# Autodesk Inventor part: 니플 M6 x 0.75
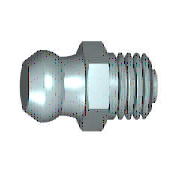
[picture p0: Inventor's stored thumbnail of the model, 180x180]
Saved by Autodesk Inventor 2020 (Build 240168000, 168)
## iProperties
Created: 2012-02
Part Number: 니플 M6 x 0.75
Material: 강철, 연강
Description: 윤활 니플, 원추 유형 A
Document SubType Name: Modeling
Standard: JIS B 1575
Designer: mduedu
Standards Organization: JIS
Language: ko-KR
Size Designation: MT 6 x 0.75
Categories: <MemberInstance><Categories><Category DisplayName="기타 부품" InternalName="5aa15e00-363f-49f2-933f-16f664388e3f" Mnemonic="OTHER"><Category DisplayName="그리스 부속품" I
Density: 7.86 g/cm^3
Mass: 3.2546 g
Surface Area: 3.29319 cm^2
Volume: 0.414071 cm^3
Appearance: 금색
IsCustomPart: 1
Author: mduedu
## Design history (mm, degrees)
sketch "스케치1"
  geometry: L1 (-8.8, 0)-(-8.8, 2.4); L2 (-8.8, 2.4)-(-7.335, 3.202); L3 (-8.8, 0)-(4.7, 0); L4 (4.7, 0)-(4.7, 1.5); L5 (4.7, 1.5)-(4, 1.5); L6 (4, 1.5)-(4, 3); L7 (4, 3)-(0, 3); L8 (-11.5, 0)-(7.4, 0) reference; L9 (0, -1.733)-(0, 10.398) reference; L10 (-3, 3.5)-(0, 3.5); L11 (0, 3.5)-(0, 3); A1 r 3.3 centre (-6.535, 0) between (-4.789, 2.8) and (-7.335, 3.202); A2 r 6 centre (-6.053, 8.665) between (-4.789, 2.8) and (-3, 3.5)
  constraints: 18 end point, 5 perpendicular, 4 point on circle, 2 centre point, 2 parallel, 2 point on line, 1 collinear, 1 vertical
  dimensions: "d0" = 13.5 distance between parallel lines of L1 L4 (= GL); "d1" = 5.6 diameter of A1.start L3 (= KGB2); "d2" = 0.7 distance between parallel lines of L4 L6 (= PHH); "d3" = 3 diameter of L5 L3 (= 0.5 x NND); "d4" = 6 diameter of L7 L3 (= NND); "d5" = 6.6 dimension on A1 L3 (= KR); "d6" = 4.8 diameter of L1.end L3 (= KGB1); "d7" = 6 radius of A2 (= RBN); "d11" = 7 diameter of L10.start L3 (= SW); "d14" = 3 distance of L10.start L10.end (= KOH); "d15" = 4 distance between parallel lines of L6 L11 (= NLG); "d61" = 7.33505 distance from line of L9 L2.end (computed from KGB1, KR, PHH, GL, NLG, VERS); "d62" = 6.53505 distance from line of L9 A1.centre (computed from NLG, GL, PHH, KR, KGB1)
revolve "본체" sketch "스케치1" stored, may be unused: angle "d25" = 90 deg
sketch "스케치2"
  geometry: L1 (2.021, 3.5)-(4.041, 0); L2 (4.041, 0)-(2.021, -3.5); L3 (2.021, -3.5)-(-2.021, -3.5); L4 (-2.021, -3.5)-(-4.041, 0); L5 (-4.041, 0)-(-2.021, 3.5); L6 (-2.021, 3.5)-(2.021, 3.5); C1 r 3.5 at (0, 0) reference; 1 further point
  constraints: 12 end point, 1 coincident, 1 horizontal, 1 tangent, 11 other
extrude "머리" join sketch "스케치2" distance "d17" = 3 (= KOH); taper "d18" = 0 deg
sketch "스케치3"
  geometry: L1 (2.687, 4.041)-(3, 4.041); L2 (3, 4.041)-(3, 3.5); L3 (3, 3.5)-(2.687, 4.041); L4 (0.313, 4.041)-(0, 4.041); L5 (0, 4.041)-(0, 3.5); L6 (0, 3.5)-(0.313, 4.041); L7 (3.6, 0)-(-0.6, 0) reference; L8 (0, 4.041)-(0, 2.021) reference; L9 (0, 4.041)-(3, 4.041) reference; L10 (3, 3.031)-(3, 4.041) reference
  constraints: 12 end point, 4 collinear, 3 perpendicular, 1 horizontal
  dimensions: "d19" = 3.5 distance from line of L5.end L7 (= 0.5 x SW); "d20" = 3.5 distance from line of L2.end L7 (= 0.5 x SW); "d21" = 30 deg angle of L6 L5; "d22" = 30 deg angle of L2 L3
revolve "모따기1" sketch "스케치3" stored, may be unused: angle "d56" = 90 deg
body "Solid1"
fillet "모깎기1" dims "d8" = 0.2 (= RR)
feature "스레드1" dims "d9" = 3.53991 (= NLG - GAL), "d10" = 0
chamfer "모따기2" distance "d23" = 0.46009 (= -0.5 x GD1 + 0.5 x NND); stored, may be unused: angle "d24" = 45 deg, second distance "d59" = 0.46009 (= -0.5 x GD1 + 0.5 x NND)
other parameters: "NLG" = 4 [user parameter; used in 4 equation terms], "GL" = 13.5 [user parameter; used in 3 equation terms], "NND" = 6 [user parameter; used in 4 equation terms], "KGB1" = 4.8 [user parameter; used in 3 equation terms], "KGB2" = 5.6 [user parameter; used in 1 equation term], "VERS" = 0.8 [user parameter; used in 1 equation term], "KR" = 6.6 [user parameter; used in 3 equation terms], "RBN" = 6 [user parameter; used in 1 equation term], "SW" = 7 [user parameter; used in 3 equation terms], "KOH" = 3 [user parameter; used in 2 equation terms], "GAL" = 0.46009 (= 0.61345 x PTC) [user parameter; used in 1 equation term], "FAWI" = 45 deg [user parameter], "PHH" = 0.7 [user parameter; used in 3 equation terms], "GD1" = 5.07983 (= THREADDIA - 1.2269 x PTC) [user parameter; used in 2 equation terms], "RR" = 0.2 [user parameter; used in 1 equation term], "d12" = 0, "d13" = 0, "GUL" = 0.46009 (= 0.61345 x PTC) [user parameter], "TPU" = 13.33333 (computed from PTC) [user parameter], "DULO" = 1.5 [user parameter], "PTC" = 0.75 [user parameter; used in 4 equation terms], "GEL" = 4 [user parameter], "THREADDIA" = 6 [user parameter; used in 1 equation term], "TOA" = 30 deg [user parameter]
